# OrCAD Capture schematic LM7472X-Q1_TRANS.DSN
size Custom; title: LM7472x-Q1 Low IQ Ideal Diode Controller With Active; rev: 1.0; note: Datasheet: SLVSFH8     EVM: PSIL174; note: Rectification
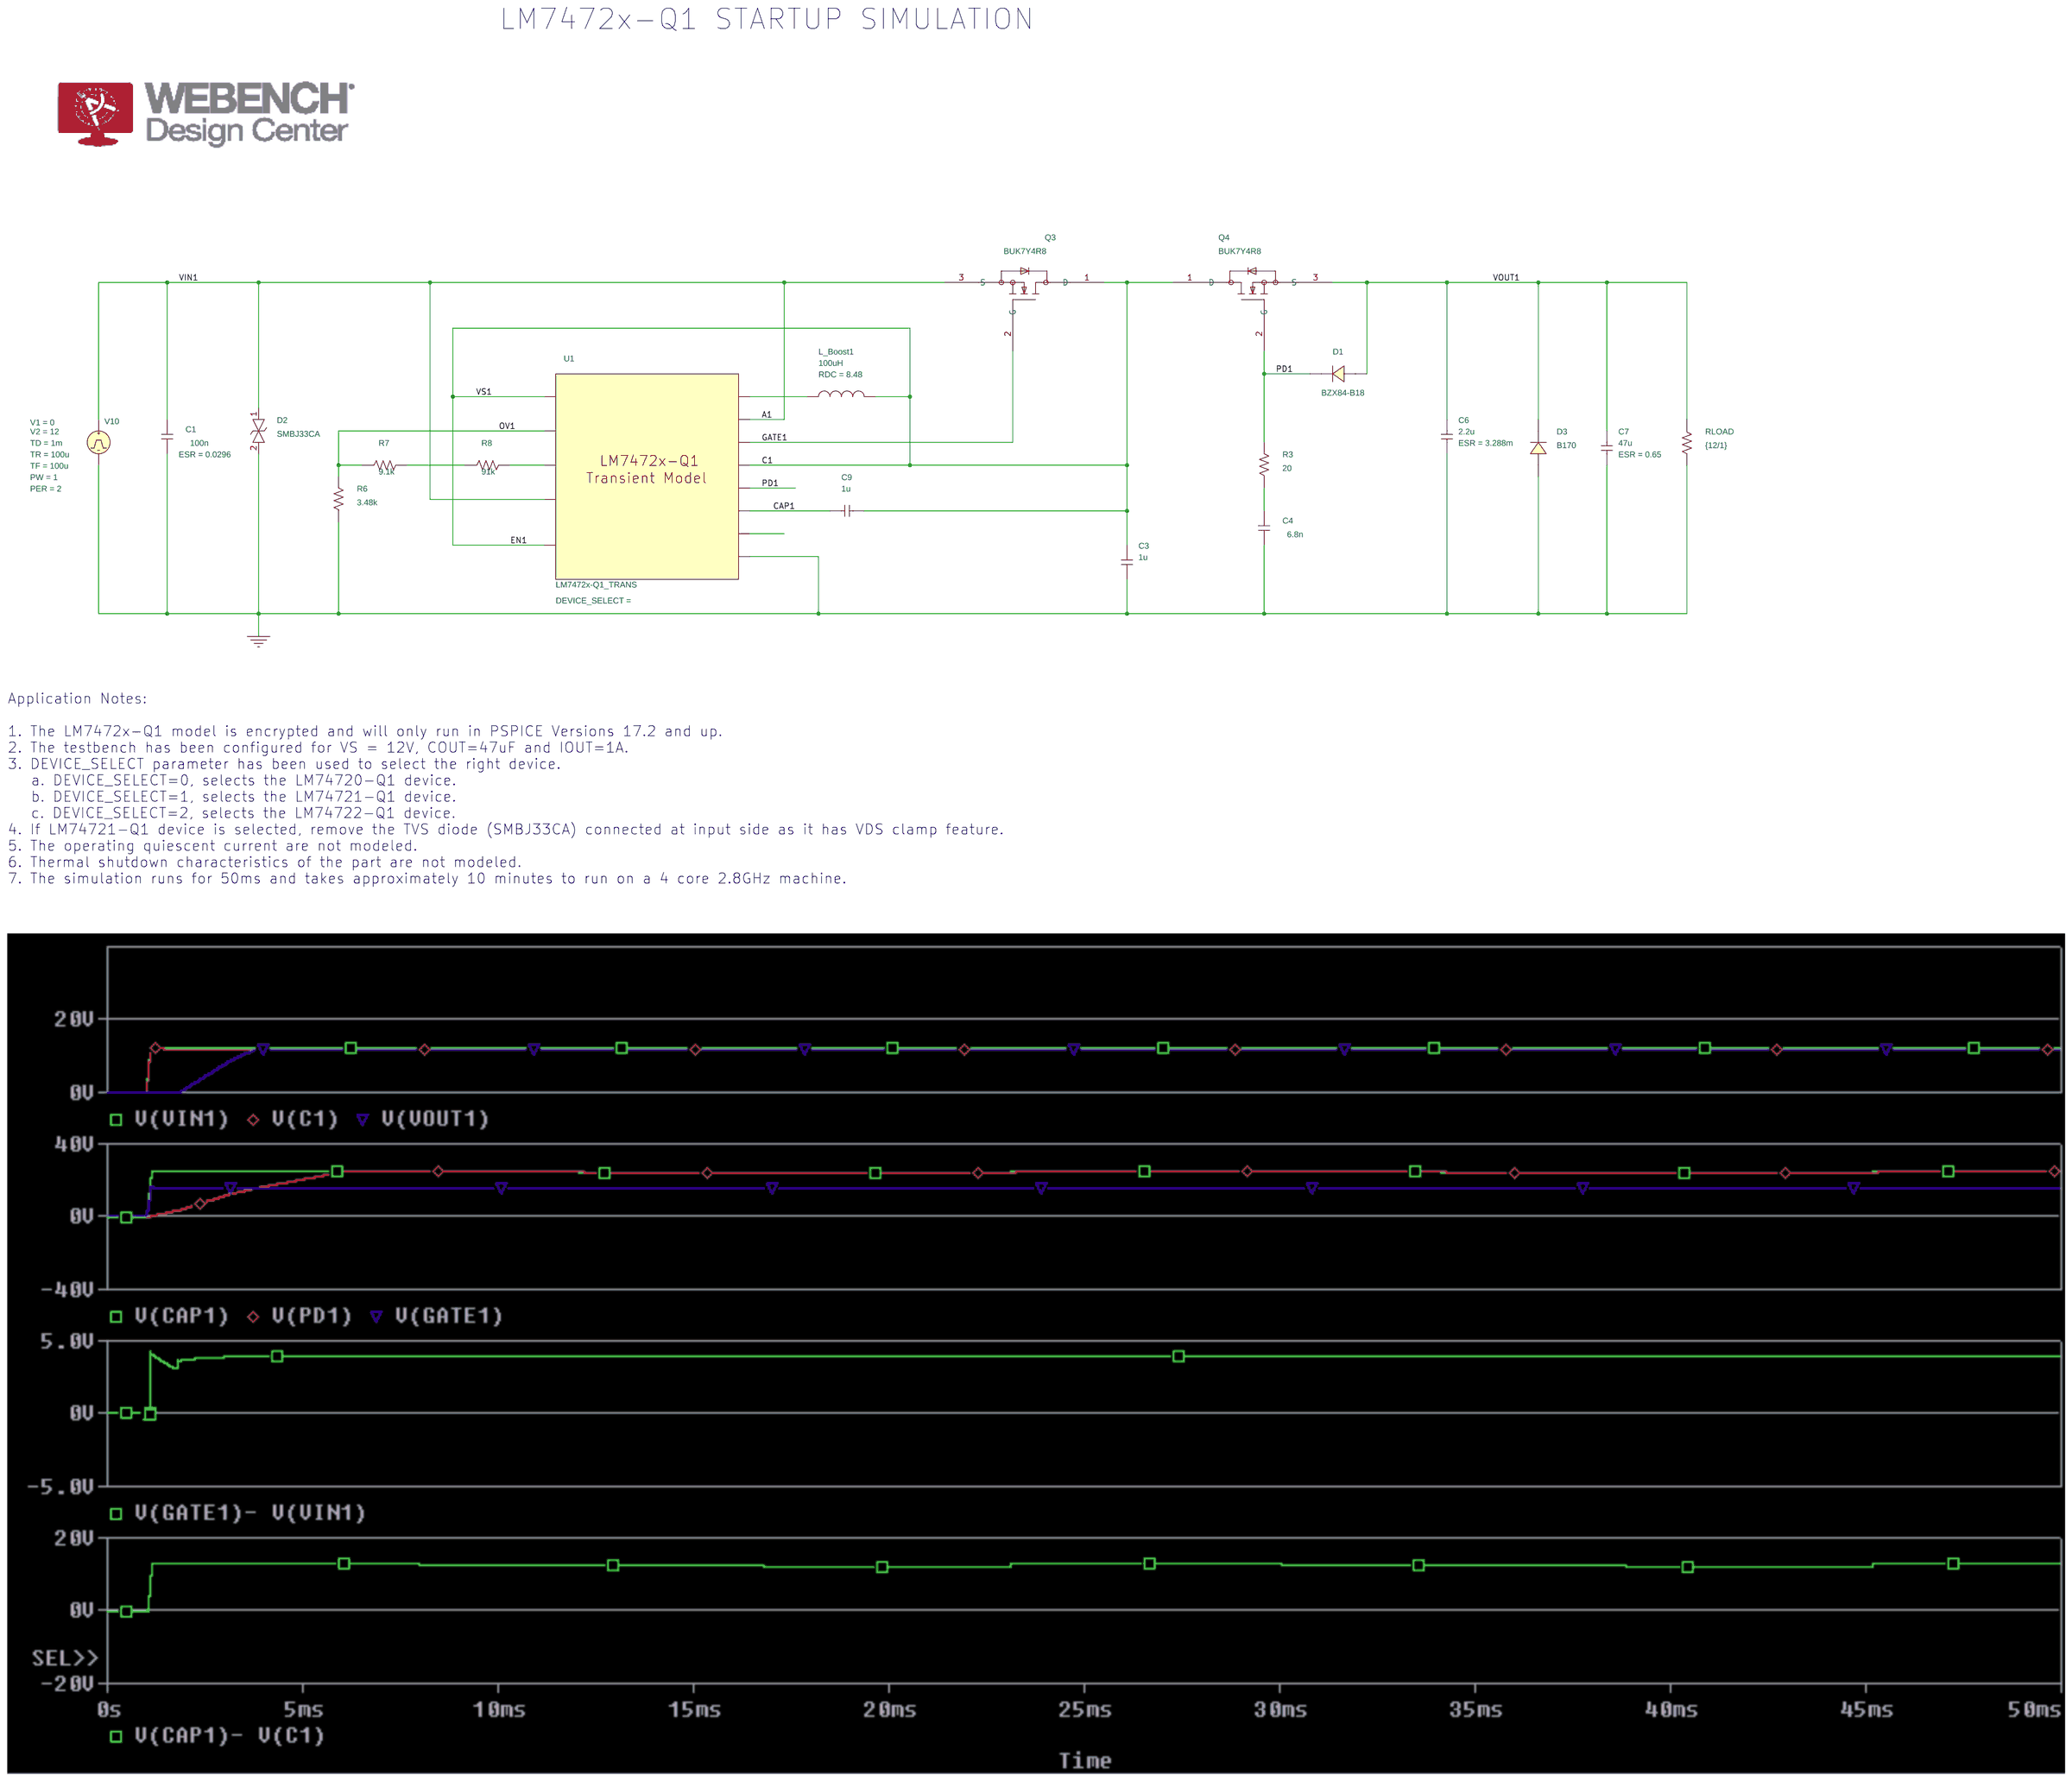
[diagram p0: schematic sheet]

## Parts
C1  100n  [RAD/CK05]
C3  1u  [cap196]
C4  6.8n  [RAD/CK05]
C6  2.2u  [RAD/CK05]
C7  47u  [RAD/CK05]
C9  1u  [cap196]
D1  BZX84-B18
D2  SMBJ33CA
D3  B170
L_Boost1  100uH  [DISC/.350x.175/LS.200x.100/.034]
Q3  BUK7Y4R8
Q4  BUK7Y4R8
R3  20  [AX/RC05]
R6  3.48k  [AX/RC05]
R7  9.1k  [AX/RC05]
R8  91k  [AX/RC05]
RLOAD  {12/1}  [AX/RC05]
U1  LM7472x-Q1_TRANS
V10  VPULSE

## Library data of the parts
C1 = C: AppProp: InductiveSlave:;SRF:;PrevCap:100n;PrevESL:; ESR: 0.0296
C3 C4 C9 = C
C6 = C: AppProp: InductiveSlave:;SRF:;PrevCap:100n;PrevESL:; ESR: 3.288m; IC: 0
C7 = C: AppProp: InductiveSlave:;SRF:;PrevCap:100n;PrevESL:; ESR: 0.65; IC: 0
D1 D3 = D_D_TPS26600: PSpiceTemplate: D^@REFDES  %A %K @MODEL ?AREA/@AREA/
D2 = SMBJ33CA_0
L_Boost1 = L: AppProp: SRF:; RDC: 8.48
Q3 Q4 = BUK7Y4R8
R3 R6-R8 RLOAD = R
U1 = LM7472x-Q1_TRANS
V10 = VPULSE: PER: 2; PW: 1; TD: 1m; TF: 100u; TR: 100u; V1: 0; V2: 12

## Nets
0: C1.2 C3.2 C4.2 C6.2 C7.2 D2.2 D3.1(A) R6.1 RLOAD.2 U1.GND V10.2(-)
A1: C1.1 D2.1 Q3.3(S) U1.A U1.VSNS V10.1(+)
C1: C3.1 C9.2 L_Boost1.2 Q3.1(D) Q4.1(D) U1.C U1.EN U1.VS
CAP1: C9.1 U1.CAP
GATE1: Q3.2(G) U1.GATE
OV1: R6.2 R7.1 U1.OV
PD1: D1.2(K) Q4.2(G) R3.2 U1.PD
VOUT1: C6.1 C7.1 D1.1(A) D3.2(K) Q4.3(S) RLOAD.1
N16773848: L_Boost1.1 U1.LX
N16774164: R7.2 R8.1
N16774170: R8.2 U1.SW
N16774236: C4.1 R3.1

Not connected (* = marked no-connect by the designer): U1 RTN

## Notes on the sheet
- LM7472x-Q1 STARTUP SIMULATION
- Application Notes:
  1. The LM7472x-Q1 model is encrypted and will only run in PSPICE Versions 17.2 and up.
  2. The testbench has been configured for VS = 12V, COUT=47uF and IOUT=1A.
  3. DEVICE_SELECT parameter has been used to select the right device.
     a. DEVICE_SELECT=0, selects the LM74720-Q1 device.
     b. DEVICE_SELECT=1, selects the LM74721-Q1 device.
     c. DEVICE_SELECT=2, selects the LM74722-Q1 device.
  4. If LM74721-Q1 device is selected, remove the TVS diode (SMBJ33CA) connected at input side as it has VDS clamp feature.
  5. The operating quiescent current are not modeled.
  6. Thermal shutdown characteristics of the part are not modeled.
  7. The simulation runs for 50ms and takes approximately 10 minutes to run on a 4 core 2.8GHz machine.
